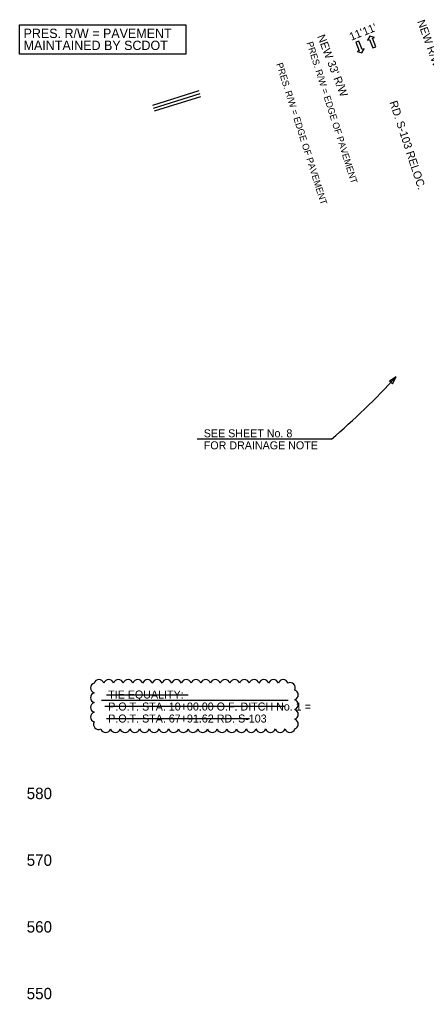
# Model space of a CAD drawing. Extents: x 1964377 to 1966966, y 1116414 to 1123213.
# Drawn here: x 1965288 to 1965594, y 1122477 to 1123211 of the extents above; entities that cross this region are included whole.
import ezdxf

# ---------------------------------------------------------------- set-up
doc = ezdxf.new("R2010")
doc.units = 0
for name, color, linetype in [('RD_DDB_Profile_Elev', 7, 'Continuous'), ('RD_EX_RW_TX', 7, 'Continuous'), ('RD_HC_Data', 7, 'Continuous'), ('RD_HC_Data_Rel', 7, 'Continuous'), ('RD_PD_Final_LnLine', 7, 'Continuous'), ('RD_PD_Final_TX', 7, 'Continuous'), ('RD_PD_RW_TX', 7, 'Continuous'), ('RD_TX_Drainage', 7, 'Continuous')]:
    doc.layers.add(name, color=color, linetype=linetype)

msp = doc.modelspace()

# ---------------------------------------------------------------- linework, layer by layer
at = {"layer": 'RD_EX_RW_TX'}
msp.add_lwpolyline([(1965288.49, 1123207.31), (1965413.19, 1123207.31), (1965413.19, 1123185.31), (1965288.49, 1123185.31)], close=True, dxfattribs=at)
at = {"layer": 'RD_HC_Data'}
for p, q in [((1965388.31, 1123146.98), (1965423.22, 1123157.89)), ((1965388.98, 1123144.83), (1965423.89, 1123155.74)), ((1965389.65, 1123142.68), (1965424.56, 1123153.59)), ((1965489.99, 1122700.71), (1965349.94, 1122700.71)), ((1965353.63, 1122704.99), (1965415.05, 1122704.99)), ((1965352.46, 1122696.4), (1965487.74, 1122696.4)), ((1965353.63, 1122687.14), (1965460.99, 1122687.14))]:
    msp.add_line(p, q, dxfattribs=at)
for centre, start, end in [((1965348.05, 1122712.61), 17.5, 162.5), ((1965355.32, 1122712.61), 17.5, 162.5), ((1965362.59, 1122712.61), 17.5, 162.5), ((1965369.87, 1122712.61), 17.5, 162.5), ((1965377.14, 1122712.61), 17.5, 162.5), ((1965384.41, 1122712.61), 17.5, 162.5), ((1965391.68, 1122712.61), 17.5, 162.5), ((1965398.95, 1122712.61), 17.5, 162.5), ((1965406.22, 1122712.61), 17.5, 162.5), ((1965413.49, 1122712.61), 17.5, 162.5), ((1965420.76, 1122712.61), 17.5, 162.5), ((1965428.03, 1122712.61), 17.5, 162.5), ((1965435.3, 1122712.61), 17.5, 162.5), ((1965442.57, 1122712.61), 17.5, 162.5), ((1965449.84, 1122712.61), 17.5, 162.5), ((1965457.11, 1122712.61), 17.5, 162.5), ((1965464.39, 1122712.61), 17.5, 162.5), ((1965471.66, 1122712.61), 17.5, 162.5), ((1965478.93, 1122712.61), 17.5, 162.5), ((1965486.2, 1122712.61), 17.5, 162.5), ((1965491.53, 1122710.34), 331.4441, 116.4441), ((1965345.56, 1122710.12), 107.5, 252.5), ((1965493.73, 1122704.89), 287.5, 72.5), ((1965345.56, 1122702.85), 107.5, 252.5), ((1965345.56, 1122695.58), 107.5, 252.5), ((1965493.73, 1122697.61), 287.5, 72.5), ((1965345.56, 1122688.31), 107.5, 252.5), ((1965493.73, 1122690.34), 287.5, 72.5), ((1965347.76, 1122682.85), 151.4441, 296.4441), ((1965493.73, 1122683.07), 287.5, 72.5), ((1965353.1, 1122680.58), 197.5, 342.5), ((1965360.37, 1122680.58), 197.5, 342.5), ((1965367.64, 1122680.58), 197.5, 342.5), ((1965374.91, 1122680.58), 197.5, 342.5), ((1965382.18, 1122680.58), 197.5, 342.5), ((1965389.45, 1122680.58), 197.5, 342.5), ((1965396.72, 1122680.58), 197.5, 342.5), ((1965403.99, 1122680.58), 197.5, 342.5), ((1965411.26, 1122680.58), 197.5, 342.5), ((1965418.53, 1122680.58), 197.5, 342.5), ((1965425.8, 1122680.58), 197.5, 342.5), ((1965433.07, 1122680.58), 197.5, 342.5), ((1965440.35, 1122680.58), 197.5, 342.5), ((1965447.62, 1122680.58), 197.5, 342.5), ((1965454.89, 1122680.58), 197.5, 342.5), ((1965462.16, 1122680.58), 197.5, 342.5), ((1965469.43, 1122680.58), 197.5, 342.5), ((1965476.7, 1122680.58), 197.5, 342.5), ((1965483.97, 1122680.58), 197.5, 342.5), ((1965491.24, 1122680.58), 197.5, 342.5)]:
    msp.add_arc(centre, 3.81, start, end, dxfattribs=at)
at = {"layer": 'RD_PD_Final_LnLine'}
for points in [[(1965553.35, 1123189.88), (1965555.59, 1123190.75), (1965553.12, 1123197.16), (1965554.64, 1123197.75), (1965551.24, 1123198.71), (1965549.36, 1123195.72), (1965550.88, 1123196.3)], [(1965542.97, 1123195.05), (1965540.73, 1123194.18), (1965543.21, 1123187.76), (1965541.69, 1123187.18), (1965545.09, 1123186.22), (1965546.97, 1123189.21), (1965545.45, 1123188.63)]]:
    msp.add_lwpolyline(points, close=True, dxfattribs=at)
at = {"layer": 'RD_TX_Drainage'}
msp.add_line((1965522.49, 1122896.51), (1965421.64, 1122896.51), dxfattribs=at)
msp.add_lwpolyline([(1965568.11, 1122938.07), (1965570.91, 1122943.37), (1965565.83, 1122940.19)], close=True, dxfattribs=at)
msp.add_arc((1965102.4, 1123379.02), 639.77, 311.04373, 317.08178, dxfattribs=at)

# ---------------------------------------------------------------- texts
at = {"layer": 'RD_DDB_Profile_Elev'}
for s, p in [('580', (1965293.84, 1122626.8)), ('570', (1965293.84, 1122576.8)), ('560', (1965293.84, 1122526.8)), ('550', (1965293.84, 1122476.8))]:
    msp.add_text(s, height=8.5, dxfattribs=at).set_placement(p)
at = {"layer": 'RD_EX_RW_TX'}
for s, p in [('PRES. R/W = PAVEMENT ', (1965291.49, 1123197.31)), ('MAINTAINED BY SCDOT', (1965291.49, 1123188.31))]:
    msp.add_text(s, height=7, dxfattribs=at).set_placement(p)
for p in [(1965503.63, 1123193.7), (1965480.9, 1123177.85)]:
    msp.add_text('PRES. R/W = EDGE OF PAVEMENT', height=5, rotation=287.62337, dxfattribs=at).set_placement(p)
at = {"layer": 'RD_HC_Data'}
for s, p in [('TIE EQUALITY:', (1965354.94, 1122702.21)), ('P.O.T. STA. 10+00.00 O.F. DITCH No. 1 =', (1965354.94, 1122693.21)), ('P.O.T. STA. 67+91.62 RD. S-103', (1965354.94, 1122684.21))]:
    msp.add_text(s, height=6, dxfattribs=at).set_placement(p)
at = {"layer": 'RD_HC_Data_Rel'}
msp.add_text('RD. S-103 RELOC.', height=6, rotation=288.23569, dxfattribs=at).set_placement((1965565.84, 1123149.16))
at = {"layer": 'RD_PD_Final_TX'}
for p in [(1965547.17, 1123199.01), (1965537.26, 1123195.21)]:
    msp.add_text("11'", height=6, rotation=22.02601, dxfattribs=at).set_placement(p)
at = {"layer": 'RD_PD_RW_TX'}
for s, rotation, p in [('NEW R/W', 289.95859, (1965586.61, 1123209.69)), ("NEW 33' R/W", 291.11491, (1965511.65, 1123198.54))]:
    msp.add_text(s, height=6, rotation=rotation, dxfattribs=at).set_placement(p)
at = {"layer": 'RD_TX_Drainage'}
for s, p in [('SEE SHEET No. 8', (1965426.64, 1122898.01)), ('FOR DRAINAGE NOTE', (1965426.64, 1122889.01))]:
    msp.add_text(s, height=6, dxfattribs=at).set_placement(p)

doc.saveas('drawing.dxf')
